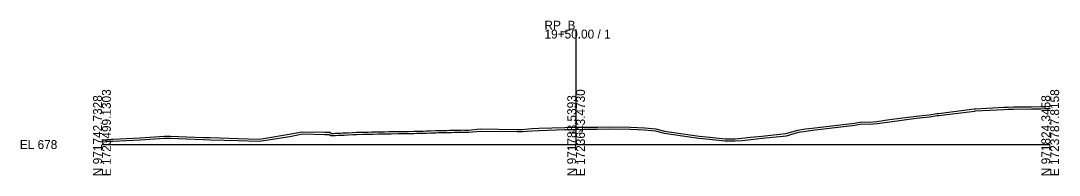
# Model space of a CAD drawing. Extents: x -26 to 1723826, y -10 to 971808.
# Drawn here: x -25.7 to 302.8, y 9490.3 to 9539.1 of the extents above; entities that cross this region are included whole.
import ezdxf

# ---------------------------------------------------------------- set-up
doc = ezdxf.new("R2010")
doc.units = 0
for name, color, linetype in [('Default', 7, 'Continuous'), ('Exist Cross Section Cell', 7, 'Continuous'), ('Exist XS Center Line Elevation Label', 7, 'Continuous'), ('Exist XS Ground Line', 7, 'Continuous')]:
    doc.layers.add(name, color=color, linetype=linetype)

msp = doc.modelspace()

# ---------------------------------------------------------------- linework, layer by layer
at = {"layer": 'Exist Cross Section Cell'}
for p, q in [((150, 9500), (150, 9536.33)), ((0, 9500), (150, 9500)), ((150, 9500), (300, 9500))]:
    msp.add_line(p, q, dxfattribs=at)
at = {"layer": 'Exist XS Ground Line'}
for points in [[(0, 9501.48), (3.01, 9501.69), (3.44, 9501.71), (12.07, 9502.17), (19.73, 9502.64), (21.72, 9502.67), (26.75, 9502.48), (32.11, 9502.27), (34.22, 9502.2), (43.1, 9501.93), (49.71, 9501.74), (51.77, 9502.07), (59.26, 9503.24), (63.37, 9504), (70.54, 9503.88), (71.06, 9503.88), (71.52, 9503.89), (72.07, 9503.9), (72.64, 9503.5), (73.27, 9503.53), (73.82, 9503.56), (74.79, 9503.61), (75.48, 9503.63), (76.21, 9503.67), (76.6, 9503.69), (77.9, 9503.75), (79.29, 9503.81), (80.5, 9503.87), (82.66, 9503.91), (83.34, 9503.92), (84.19, 9503.95), (85.37, 9503.98), (85.7, 9503.99), (87.4, 9504.02), (88.3, 9504.03), (89.43, 9504.05), (90.9, 9504.08), (91.45, 9504.08), (93.66, 9504.12), (96.5, 9504.17), (96.97, 9504.18), (98.66, 9504.2), (99.54, 9504.23), (101.26, 9504.26), (101.57, 9504.26), (102.63, 9504.29), (103.85, 9504.33), (105.61, 9504.4), (106.44, 9504.43), (107.95, 9504.46), (109.05, 9504.48), (109.95, 9504.51), (110.49, 9504.53), (111.5, 9504.56), (111.83, 9504.57), (113.64, 9504.6), (114.23, 9504.61), (114.79, 9504.6), (115.98, 9504.6), (119.63, 9504.95), (131.34, 9504.78), (132.38, 9504.78), (132.98, 9504.8), (136, 9505.03), (138.25, 9505.13), (146.41, 9505.41), (150, 9505.47), (152.44, 9505.51), (156.8, 9505.55), (160.54, 9505.6), (167.19, 9505.52), (171.69, 9505.3), (175.25, 9505), (177.99, 9504.25), (186.72, 9502.99), (188.92, 9502.65), (192.28, 9502.33), (197.11, 9501.81), (200.32, 9501.81), (202.46, 9501.98), (205.17, 9502.31), (208.75, 9502.7), (216.38, 9503.46), (220.19, 9504.59), (222.61, 9504.93), (224.68, 9505.23), (238.02, 9506.78), (240.28, 9507.22), (242.71, 9507.07), (245.17, 9507.31), (249.18, 9507.88), (257.55, 9509), (261.69, 9509.41), (264.13, 9509.81), (264.69, 9509.85), (265.48, 9509.9), (275.94, 9511.27), (276.33, 9511.29), (285.35, 9511.8), (286.66, 9511.83), (288.4, 9511.88), (294.07, 9511.92), (296.97, 9512.01), (298.31, 9512.06), (300, 9512.11)], [(0.05, 9500.82), (3.05, 9501.02), (3.48, 9501.05), (12.11, 9501.51), (19.76, 9501.97), (21.71, 9502), (26.72, 9501.81), (32.08, 9501.61), (34.2, 9501.53), (43.08, 9501.27), (49.75, 9501.07), (51.88, 9501.41), (59.38, 9502.59), (63.42, 9503.34), (70.54, 9503.22), (71.07, 9503.22), (71.53, 9503.22), (71.87, 9503.23), (72.45, 9502.82), (73.3, 9502.86), (73.85, 9502.89), (74.82, 9502.94), (75.51, 9502.96), (76.25, 9503), (76.63, 9503.02), (77.93, 9503.08), (79.32, 9503.14), (80.52, 9503.2), (82.68, 9503.24), (83.36, 9503.26), (84.21, 9503.28), (85.39, 9503.32), (85.72, 9503.33), (87.41, 9503.36), (88.31, 9503.37), (89.44, 9503.38), (90.91, 9503.41), (91.46, 9503.42), (93.67, 9503.46), (96.51, 9503.5), (96.98, 9503.51), (98.68, 9503.54), (99.55, 9503.56), (101.28, 9503.59), (101.58, 9503.6), (102.65, 9503.63), (103.88, 9503.66), (105.63, 9503.74), (106.46, 9503.77), (107.96, 9503.79), (109.07, 9503.81), (109.97, 9503.84), (110.51, 9503.86), (111.52, 9503.9), (111.85, 9503.9), (113.65, 9503.93), (114.23, 9503.94), (114.79, 9503.94), (116.01, 9503.93), (119.65, 9504.28), (131.33, 9504.11), (132.38, 9504.12), (133.01, 9504.13), (136.04, 9504.37), (138.28, 9504.47), (146.43, 9504.74), (150.01, 9504.8), (152.45, 9504.84), (156.81, 9504.88), (160.54, 9504.94), (167.17, 9504.85), (171.64, 9504.64), (175.14, 9504.34), (177.85, 9503.59), (186.62, 9502.33), (188.83, 9501.99), (192.22, 9501.66), (197.08, 9501.14), (200.35, 9501.15), (202.53, 9501.32), (205.24, 9501.65), (208.82, 9502.04), (216.51, 9502.8), (220.33, 9503.94), (222.7, 9504.27), (224.77, 9504.56), (238.13, 9506.12), (240.32, 9506.55), (242.72, 9506.41), (245.25, 9506.65), (249.28, 9507.22), (257.63, 9508.34), (261.77, 9508.75), (264.21, 9509.15), (264.73, 9509.19), (265.55, 9509.24), (276, 9510.6), (276.37, 9510.62), (285.37, 9511.13), (286.68, 9511.17), (288.41, 9511.21), (294.08, 9511.25), (296.99, 9511.34), (298.33, 9511.39), (300.02, 9511.44)]]:
    msp.add_lwpolyline(points, dxfattribs=at)

# ---------------------------------------------------------------- texts
at = {"layer": 'Default'}
msp.add_text('-', height=0.0001, dxfattribs=at).set_placement((0, 9500))
at = {"layer": 'Exist Cross Section Cell'}
for s, p in [('RP_B', (140, 9536.33)), ('19+50.00 / 1', (140, 9533.53)), ('EL 678', (-26, 9498.6))]:
    msp.add_text(s, height=2.8, dxfattribs=at).set_placement(p)
for s, p in [('N 971742.7328', (0, 9490)), ('E 1723499.1303', (2.8, 9490)), ('N 971783.5393', (150, 9490)), ('E 1723643.4730', (152.8, 9490)), ('N 971824.3458', (300, 9490)), ('E 1723787.8158', (302.8, 9490))]:
    msp.add_text(s, height=2.8, rotation=90, dxfattribs=at).set_placement(p)
at = {"layer": 'Exist XS Center Line Elevation Label'}
msp.add_text('683.47', height=1, dxfattribs=at).set_placement((147.84, 9503.31))

doc.saveas('drawing.dxf')
